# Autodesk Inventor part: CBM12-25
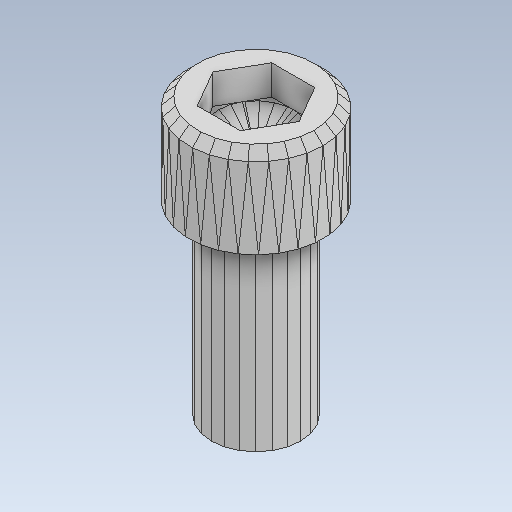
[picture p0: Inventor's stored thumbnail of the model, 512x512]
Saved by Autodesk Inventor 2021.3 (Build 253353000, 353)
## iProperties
Created: 2022-02
Part Number: CBM12-25
Material: 一般
Document SubType Name: Modeling
Designer: kengo
Density: 1 g/cm^3
Appearance: 既定
Author: kengo
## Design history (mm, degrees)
feature "CBM12-25"
node "ソリッド1"
